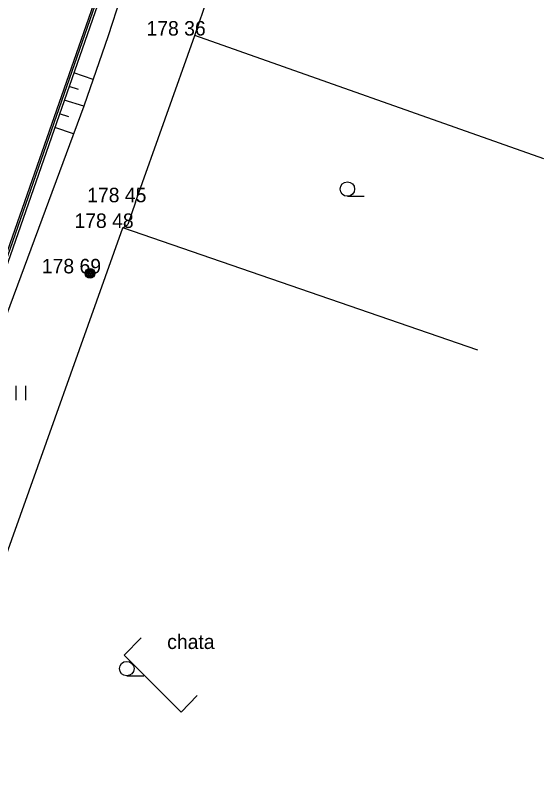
# Model space of a CAD drawing. Extents: x -537755 to -537431, y -1180722 to -1180510.
# Drawn here: x -537467.76 to -537440.39, y -1180613.62 to -1180574.05 of the extents above; entities that cross this region are included whole.
import ezdxf

# ---------------------------------------------------------------- set-up
doc = ezdxf.new("R2010")
doc.units = 0
for name, color, linetype in [('Vrstva 1', 7, 'Continuous'), ('Vrstva 14', 7, 'Continuous'), ('Vrstva 15', 7, 'Continuous'), ('Vrstva 25', 7, 'Continuous'), ('Vrstva 3', 7, 'Continuous'), ('Vrstva 36', 7, 'Continuous'), ('Vrstva 41', 7, 'Continuous'), ('Vrstva 5', 7, 'Continuous'), ('Vrstva 7', 7, 'Continuous'), ('Vrstva 8', 7, 'Continuous')]:
    doc.layers.add(name, color=color, linetype=linetype)

msp = doc.modelspace()

# ---------------------------------------------------------------- linework, layer by layer
at = {"layer": 'Vrstva 1'}
for p, q in [((-537462.95, -1180575.12), (-537462.95, -1180575.12)), ((-537458.47, -1180575.1), (-537458.47, -1180575.1)), ((-537464.22, -1180578.75), (-537464.22, -1180578.75)), ((-537461.54, -1180583.73), (-537461.54, -1180583.73)), ((-537461.94, -1180584.88), (-537461.94, -1180584.88)), ((-537462.2, -1180585.06), (-537462.2, -1180585.06)), ((-537463.89, -1180587.41), (-537463.89, -1180587.41)), ((-537463.81, -1180587.49), (-537463.81, -1180587.49))]:
    msp.add_line(p, q, dxfattribs=at)
at = {"layer": 'Vrstva 14'}
for p, q in [((-537462.95, -1180575.12), (-537464.22, -1180578.75)), ((-537464.22, -1180578.75), (-537468.22, -1180589.56))]:
    msp.add_line(p, q, dxfattribs=at)
msp.add_lwpolyline([(-537461.28, -1180566.15), (-537460.5, -1180567.93), (-537461.68, -1180571.17), (-537462.95, -1180575.12)], dxfattribs=at)
at = {"layer": 'Vrstva 15'}
for p, q in [((-537463.736, -1180577.368), (-537464.732, -1180577.021)), ((-537464.495, -1180577.897), (-537464.979, -1180577.729)), ((-537464.22, -1180578.75), (-537465.226, -1180578.437)), ((-537464.989, -1180579.314), (-537465.473, -1180579.145)), ((-537464.753, -1180580.19), (-537465.72, -1180579.853))]:
    msp.add_line(p, q, dxfattribs=at)
at = {"layer": 'Vrstva 25'}
for radius in [0.25, 0.2, 0.15, 0.1, 0.05]:
    msp.add_circle((-537463.89, -1180587.41), radius, dxfattribs=at)
at = {"layer": 'Vrstva 36'}
for p, q in [((-537450.564, -1180583.418), (-537449.689, -1180583.418)), ((-537467.723, -1180593.974), (-537467.723, -1180593.224)), ((-537467.223, -1180593.974), (-537467.223, -1180593.224)), ((-537461.989, -1180608.248), (-537461.114, -1180608.248))]:
    msp.add_line(p, q, dxfattribs=at)
for centre in [(-537450.564, -1180583.043), (-537461.989, -1180607.873)]:
    msp.add_circle(centre, 0.375, dxfattribs=at)
at = {"layer": 'Vrstva 5'}
for p, q in [((-537461.236, -1180606.271), (-537462.12, -1180607.182)), ((-537462.12, -1180607.182), (-537459.18, -1180610.123)), ((-537459.18, -1180610.123), (-537458.351, -1180609.271))]:
    msp.add_line(p, q, dxfattribs=at)
at = {"layer": 'Vrstva 7'}
for p, q in [((-537477.608, -1180613.623), (-537461.55, -1180567.55)), ((-537461.41, -1180567.5), (-537475.176, -1180606.957)), ((-537461.663, -1180567.617), (-537473.031, -1180600.103)), ((-537458.47, -1180575.1), (-537456.88, -1180570.41)), ((-537461.54, -1180583.73), (-537458.47, -1180575.1)), ((-537440.393, -1180581.481), (-537458.47, -1180575.1)), ((-537462.2, -1180585.06), (-537461.94, -1180584.88)), ((-537468.4, -1180602.45), (-537462.2, -1180585.06)), ((-537443.801, -1180591.389), (-537462.2, -1180585.06))]:
    msp.add_line(p, q, dxfattribs=at)
at = {"layer": 'Vrstva 8'}
msp.add_line((-537461.54, -1180583.73), (-537461.94, -1180584.88), dxfattribs=at)

# ---------------------------------------------------------------- texts
at = {"layer": 'Vrstva 3'}
for s, p in [('178 36 ', (-537460.97, -1180575.1)), ('178 45 ', (-537464.04, -1180583.73)), ('178 48 ', (-537464.7, -1180585.06)), ('178 69 ', (-537466.39, -1180587.41))]:
    msp.add_text(s, height=0.75, dxfattribs=at).set_placement(p)
at = {"layer": 'Vrstva 41'}
msp.add_text('chata', height=0.75, dxfattribs=at).set_placement((-537459.896, -1180606.857))

doc.saveas('drawing.dxf')
